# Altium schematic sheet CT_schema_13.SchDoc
size 145 x 119 mm
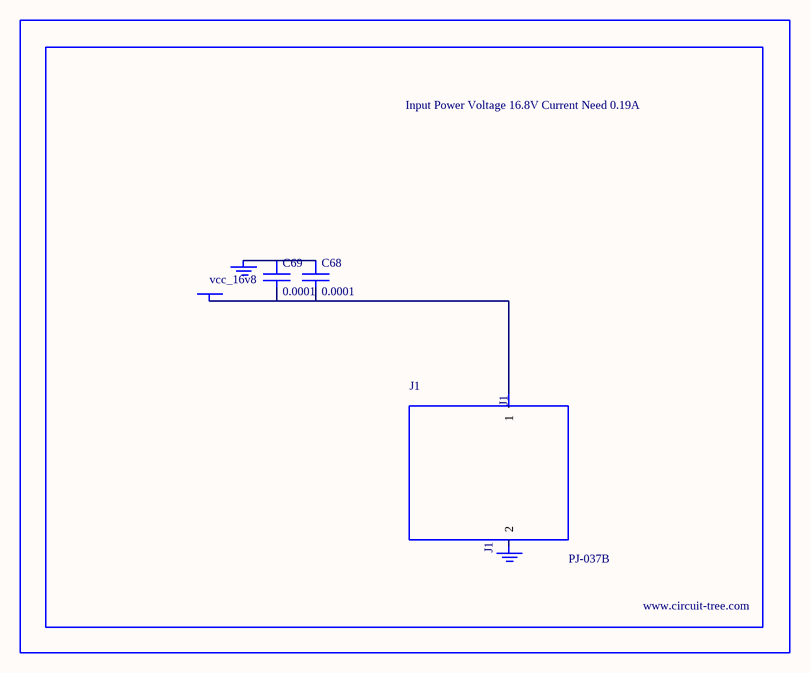
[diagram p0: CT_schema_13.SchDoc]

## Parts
BORDER12  (no value)
C68  0.0001  [EXV-9H]
C69  0.0001  [EXV-9H]
GND_INSTANCE_12_0  (no value)
GND_INSTANCE_12_1  (no value)
J1  PJ-037B  [PJ-037B_PACKAGE]
POWER_INSTANCE_12_0  vcc_16v8

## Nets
NetC68_1: C68.1 C69.1 GND_INSTANCE_12_0.0(GND)
NetC68_2: C68.2 C69.2 J1.1 POWER_INSTANCE_12_0.0(PWR)

Not connected (* = marked no-connect by the designer): GND_INSTANCE_12_1 0(GND); J1 2

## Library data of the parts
BORDER12 = BORDER_PAGE12
C68 C69 = EDK107M035A9HAA
GND_INSTANCE_12_0 GND_INSTANCE_12_1 = GND
POWER_INSTANCE_12_0 = PWR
